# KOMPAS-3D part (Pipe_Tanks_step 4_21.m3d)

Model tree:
1. X Axis
2. Y Axis
3. Z Axis  (labels: Bend 90 Dn 20; Pipe Dn 20)
     Òîëùèíà ñòåíêè 1 = 1

Referenced files in C:\Documents and Settings\kashirsky\Мои документы\Camtasia Studio\Pipelines3D\Tanks\: Tanks_step 4.a3d
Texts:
  Pipe Dn 50
  Steel ASTM A295
  Three Point Plane
  Plane at Angle
  Line and Point Plane
  Axis through Two Vertices
  Axis of Feature
  Axis of Conical Surface
  Axis through Edge
  Trim by Surface
  Trim by Sketch
  Feature with No History
  Intersection Axis of Two Planes
  Two Line Plane
  Line and Face Plane
  Bend by line
  Hole in sheet body
  Cut in sheet body
  Point in CM
  Linear Dimension from Line to Point
  Surface Finish Symbol
  Geometric Tolerance Symbol
  Leader #1
  Leader #2
  Leader #3
  Shape Deviations and Datum
  Node point number
  Mark of coordination axis
  Node point designation
  Mark/Reference designation with leader
  Mark/reference designation on line
  Mark/Reference designation without leader
  Bend 90 Dn 20
  Pipe Dn 20
  Plane of section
